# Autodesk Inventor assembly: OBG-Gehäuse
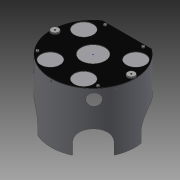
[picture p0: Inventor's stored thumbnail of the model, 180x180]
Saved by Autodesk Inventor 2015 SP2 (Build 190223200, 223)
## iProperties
Created: 2012-10
Part Number: OBG-Gehäuse
Document SubType Name: Assembly
Designer: rYan
Mass: 271.411 g
Surface Area: 2309.43 cm^2
Volume: 140.489 cm^3
Density: 1.93191 g/cm^3
Author: rYan
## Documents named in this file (7)
- D:\TIGERs GIT\Hardware\mechanik\2016\Inventor\Gehäuse\OBG-Gehäuse.iam
- D:\TIGERs GIT\Hardware\mechanik\2016\Inventor\Gehäuse\MG-Deckel.iam
- MG-Deckel.iam
- D:\TIGERs GIT\Hardware\mechanik\2016\Inventor\Inhaltscenter\de-DE\DIN 467\DIN 467 - M4.ipt
- D:\TIGERs GIT\Hardware\mechanik\2016\Inventor\Gehäuse\Gehaeuse Blech.ipt
- D:\TIGERs GIT\Hardware\mechanik\2016\Inventor\Gehäuse\Verbindungplatte Deckel.ipt
- D:\TIGERs GIT\Hardware\mechanik\2016\Inventor\Inhaltscenter\de-DE\DIN 7984\DIN 7984 - M3 x 8.ipt
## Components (7 placed, 5 different names)
1. Verbindungsplatte Deckel:1 — Passend:1, Winkel:1, Fluchtend:1, Einfügen:33, Einfügen:34
2. MG-Deckel:1 [sub-assembly] — Einfügen:19, Einfügen:20, Einfügen:33, Einfügen:34
3. DIN 467 M4:1 — Einfügen:20
4. DIN 467 M4:2 — Einfügen:19
5. Gehaeuse Blech:1 — Passend:1, Winkel:1, Fluchtend:1, Einfügen:35, Einfügen:36
6. DIN 7984 M3 x 8:1 — Einfügen:35
7. DIN 7984 M3 x 8:2 — Einfügen:36
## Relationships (9: Insert 6, Mate 1, Angle 1, Flush 1)
- Einfügen:19 [Insert]: MG-Deckel:1 ↔ DIN 467 M4:2
- Einfügen:20 [Insert]: MG-Deckel:1 ↔ DIN 467 M4:1
- Passend:1 [Mate]: Verbindungsplatte Deckel:1 ↔ Gehaeuse Blech:1
- Winkel:1 [Angle]: Verbindungsplatte Deckel:1 ↔ Gehaeuse Blech:1
- Fluchtend:1 [Flush]: Verbindungsplatte Deckel:1 ↔ Gehaeuse Blech:1
- Einfügen:33 [Insert]: Verbindungsplatte Deckel:1 ↔ MG-Deckel:1
- Einfügen:34 [Insert]: Verbindungsplatte Deckel:1 ↔ MG-Deckel:1
- Einfügen:35 [Insert]: Gehaeuse Blech:1 ↔ DIN 7984 M3 x 8:1
- Einfügen:36 [Insert]: Gehaeuse Blech:1 ↔ DIN 7984 M3 x 8:2
